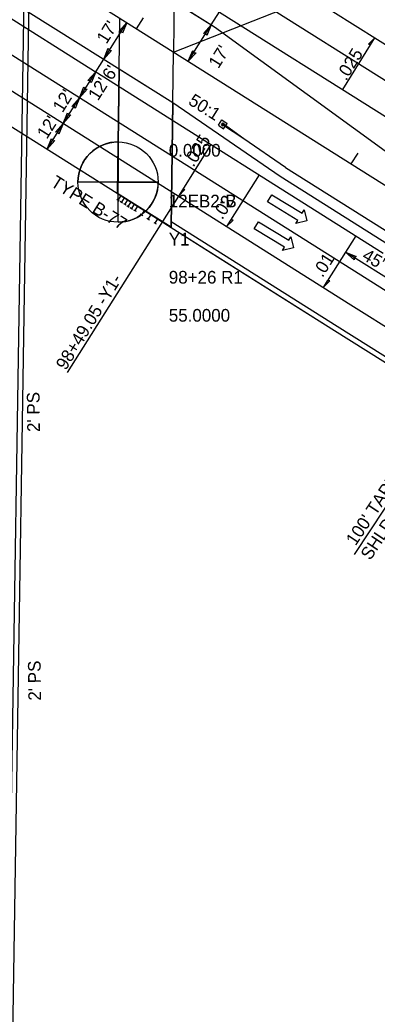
# Model space of a CAD drawing. Extents: x 2389694 to 2405615, y 546931 to 573532.
# Drawn here: x 2397764.3 to 2397905.2, y 552684.1 to 553075.7 of the extents above; entities that cross this region are included whole.
import ezdxf

# ---------------------------------------------------------------- set-up
doc = ezdxf.new("R2010")
doc.units = 0
for name, color, linetype in [('Boring Cell', 7, 'Continuous'), ('Old_Level_22', 7, 'Continuous'), ('Prop Approach Slab', 7, 'Continuous'), ('Prop Approach Slab Hatching', 7, 'Continuous'), ('Prop Cable Guiderail Anchor Unit CELL', 7, 'Continuous'), ('Prop Cable Guiderail Double Face', 7, 'Continuous'), ('Prop Conc Expressway Gutter', 7, 'Continuous'), ('Prop Dimension', 7, 'Continuous'), ('Prop Dimension Text', 7, 'Continuous'), ('Prop EOT', 7, 'Continuous'), ('Prop Guardrail', 7, 'Continuous'), ('Prop Horizontal Alignment', 7, 'Continuous'), ('Prop Horizontal Alignment Tick Small', 7, 'Continuous'), ('Prop Lane Arrow Through CELL', 7, 'Continuous'), ('Prop Lane Lines', 7, 'Continuous'), ('Prop Road Plan_ Boring - Labels from Geopak', 7, 'Continuous'), ('Prop SAU III Approach CELL', 7, 'Continuous'), ('Prop Super Arrow 1 Lane CELL', 7, 'Continuous'), ('Prop Superelevation Label', 7, 'Continuous')]:
    doc.layers.add(name, color=color, linetype=linetype)

msp = doc.modelspace()

# ---------------------------------------------------------------- linework, layer by layer
at = {"layer": 'Boring Cell'}
for p, q in [((2397803.04, 552996.02), (2397803.04, 553027.64)), ((2397803.22, 553027.64), (2397803.04, 553027.64)), ((2397818.85, 553011.83), (2397787.23, 553011.83)), ((2397818.85, 553011.83), (2397818.85, 553012.01))]:
    msp.add_line(p, q, dxfattribs=at)
for points in [[(2397803.04, 553027.64), (2397803.04, 553011.83), (2397787.23, 553011.83)], [(2397803.04, 552996.02), (2397803.04, 553011.83), (2397818.85, 553011.83)]]:
    msp.add_lwpolyline(points, dxfattribs=at)
msp.add_circle((2397803.04, 553011.83), 15.81, dxfattribs=at)
for start, end in [(89.3557, 180), (270, 0.6443)]:
    msp.add_arc((2397803.04, 553011.83), 15.81, start, end, dxfattribs=at)
at = {"layer": 'Prop Approach Slab'}
for p, q in [((2397670.86, 553139.97), (2397824.62, 553043.14)), ((2397670.16, 553090.81), (2397823.92, 552993.99)), ((2397803.47, 553056.47), (2397802.76, 553007.31))]:
    msp.add_line(p, q, dxfattribs=at)
at = {"layer": 'Prop Approach Slab Hatching'}
msp.add_lwpolyline([(2397803.47, 553056.47), (2397824.62, 553043.14), (2397823.92, 552993.99), (2397802.76, 553007.31)], close=True, dxfattribs=at)
at = {"layer": 'Prop Cable Guiderail Anchor Unit CELL'}
for p, q in [((2397842.59, 553034.24), (2397844.01, 553036.3)), ((2397843.77, 553034.31), (2397844.36, 553035.17)), ((2397844.01, 553036.3), (2397846.06, 553034.88)), ((2397844.29, 553033.96), (2397844.88, 553034.81)), ((2397844.36, 553035.17), (2397844.88, 553034.81)), ((2397852.56, 553028.89), (2397844.49, 553034.76)), ((2397844.65, 553032.82), (2397846.06, 553034.88)), ((2397842.59, 553034.24), (2397844.65, 553032.82)), ((2397843.77, 553034.31), (2397844.29, 553033.96)), ((2397852.56, 553028.89), (2397844.19, 553034.37)), ((2397852.56, 553028.89), (2397844.33, 553034.56)), ((2397869.03, 553017.54), (2397852.56, 553028.89)), ((2397852.56, 553028.89), (2397852.56, 553028.89))]:
    msp.add_line(p, q, dxfattribs=at)
at = {"layer": 'Prop Cable Guiderail Double Face'}
msp.add_line((2397869.03, 553017.54), (2397911.83, 552990.59), dxfattribs=at)
at = {"layer": 'Prop Conc Expressway Gutter'}
for p, q in [((2397824.01, 552996.26), (2397889.45, 552955.05)), ((2397889.45, 552955.05), (2397919.6, 552936.07))]:
    msp.add_line(p, q, dxfattribs=at)
at = {"layer": 'Prop Dimension'}
for p, q in [((2397825.91, 553132.18), (2397824.91, 553063.05)), ((2397824.91, 553063.05), (2397970.44, 553120.26)), ((2397839.78, 553073.78), (2397842.98, 553078.86)), ((2397797.41, 553060.28), (2397806.47, 553074.66)), ((2397802.76, 553007.31), (2397803.75, 553076.38)), ((2397830.72, 553059.39), (2397839.78, 553073.78)), ((2397823.92, 552993.99), (2397824.91, 553063.05)), ((2397794.22, 553055.2), (2397797.41, 553060.28)), ((2397787.82, 553045.05), (2397794.22, 553055.2)), ((2397781.43, 553034.89), (2397787.82, 553045.05)), ((2397775.05, 553024.76), (2397781.43, 553034.89)), ((2397826.81, 553006.32), (2397783.04, 552936.81)), ((2397930.74, 552960.25), (2397892.66, 552984.22)), ((2397924.03, 552907.26), (2397896.07, 552865.17))]:
    msp.add_line(p, q, dxfattribs=at)
for points in [[(2397803.42, 553071.27), (2397806.47, 553074.66), (2397804.74, 553070.41), (2397804.37, 553071.32)], [(2397836.73, 553070.38), (2397839.78, 553073.78), (2397838.05, 553069.52), (2397837.68, 553070.44)], [(2397800.47, 553063.67), (2397797.41, 553060.28), (2397799.15, 553064.53), (2397799.52, 553063.62)], [(2397833.78, 553062.79), (2397830.72, 553059.39), (2397832.46, 553063.65), (2397832.83, 553062.74)], [(2397791.16, 553051.81), (2397794.22, 553055.2), (2397792.48, 553050.95), (2397792.11, 553051.86)], [(2397790.88, 553048.44), (2397787.82, 553045.05), (2397789.56, 553049.3), (2397789.93, 553048.39)], [(2397784.77, 553041.65), (2397787.82, 553045.05), (2397786.09, 553040.79), (2397785.72, 553041.7)], [(2397784.48, 553038.29), (2397781.43, 553034.89), (2397783.16, 553039.15), (2397783.53, 553038.23)], [(2397778.37, 553031.5), (2397781.43, 553034.89), (2397779.69, 553030.64), (2397779.32, 553031.55)], [(2397778.1, 553028.16), (2397775.05, 553024.76), (2397776.78, 553029.02), (2397777.15, 553028.1)], [(2397896.06, 552981.17), (2397892.66, 552984.22), (2397896.92, 552982.49), (2397896, 552982.12)]]:
    msp.add_lwpolyline(points, close=True, dxfattribs=at)
at = {"layer": 'Prop EOT'}
for p, q in [((2397759.5, 552671.75), (2397782.16, 554116.88)), ((2397761.5, 552671.72), (2397784.16, 554116.85)), ((2396983.48, 553620.08), (2397932.08, 553022.75)), ((2396958.97, 553581.15), (2397793.8, 553055.47)), ((2397200.04, 553400.99), (2397894.78, 552963.52)), ((2397640.1, 553234.97), (2397944.87, 553043.06)), ((2397825.2, 553082.96), (2397841.06, 553072.97)), ((2397841.06, 553072.97), (2397967.73, 552980.9)), ((2397793.84, 553055.44), (2397907.57, 552983.82)), ((2397824.63, 553043.21), (2397866.9, 553014.16)), ((2397866.9, 553014.16), (2397909.7, 552987.21)), ((2397823.92, 552993.96), (2397888.38, 552953.36)), ((2397894.78, 552963.51), (2397922, 552946.37)), ((2397888.39, 552953.36), (2397915.61, 552936.22))]:
    msp.add_line(p, q, dxfattribs=at)
at = {"layer": 'Prop Guardrail'}
for p, q in [((2397819.91, 553086.29), (2397841.06, 553072.97)), ((2397841.06, 553072.97), (2397967.73, 552980.9)), ((2397818.63, 552997.32), (2397839.76, 552983.98)), ((2397839.76, 552983.98), (2397888.39, 552953.36)), ((2397888.39, 552953.36), (2397915.61, 552936.22))]:
    msp.add_line(p, q, dxfattribs=at)
at = {"layer": 'Prop Horizontal Alignment'}
msp.add_line((2396971.22, 553600.62), (2397933.44, 552994.72), dxfattribs=at)
at = {"layer": 'Prop Horizontal Alignment Tick Small'}
for p, q in [((2397810.35, 553072.23), (2397813.01, 553076.46)), ((2397894.97, 553018.94), (2397897.63, 553023.17))]:
    msp.add_line(p, q, dxfattribs=at)
at = {"layer": 'Prop Lane Arrow Through CELL'}
for p, q in [((2397861.91, 553003.99), (2397863.61, 553006.81)), ((2397873.89, 552996.74), (2397861.91, 553003.99)), ((2397863.61, 553006.81), (2397875.59, 552999.56)), ((2397875.59, 552999.56), (2397876.37, 553000.85)), ((2397876.37, 553000.85), (2397877.46, 552996.56)), ((2397856.66, 552993.39), (2397858.37, 552996.21)), ((2397858.37, 552996.21), (2397870.35, 552988.97)), ((2397873.11, 552995.46), (2397873.89, 552996.74)), ((2397877.46, 552996.56), (2397873.11, 552995.46)), ((2397868.64, 552986.15), (2397856.66, 552993.39)), ((2397870.35, 552988.97), (2397871.12, 552990.25)), ((2397871.12, 552990.25), (2397872.21, 552985.97)), ((2397867.86, 552984.86), (2397868.64, 552986.15)), ((2397872.21, 552985.97), (2397867.86, 552984.86))]:
    msp.add_line(p, q, dxfattribs=at)
at = {"layer": 'Prop Lane Lines'}
for p, q in [((2396989.87, 553630.23), (2397938.47, 553032.9)), ((2396952.57, 553571), (2397901.17, 552973.67)), ((2397901.18, 552973.67), (2397928.4, 552956.53))]:
    msp.add_line(p, q, dxfattribs=at)
at = {"layer": 'Prop SAU III Approach CELL'}
for p, q in [((2397802.76, 553007.31), (2397818.63, 552997.32)), ((2397802.54, 553005.09), (2397803.51, 553004.48)), ((2397804.09, 553006.48), (2397803.02, 553004.78)), ((2397803.86, 553004.26), (2397804.83, 553003.65)), ((2397805.41, 553005.64), (2397804.34, 553003.95)), ((2397805.18, 553003.42), (2397806.15, 553002.81)), ((2397806.73, 553004.81), (2397805.67, 553003.12)), ((2397808.05, 553003.98), (2397806.99, 553002.29)), ((2397806.5, 553002.59), (2397807.47, 553001.98)), ((2397807.83, 553001.76), (2397808.79, 553001.15)), ((2397809.38, 553003.15), (2397808.31, 553001.45)), ((2397809.15, 553000.93), (2397810.12, 553000.32)), ((2397810.7, 553002.31), (2397809.63, 553000.62)), ((2397813.34, 553000.65), (2397812.28, 552998.96)), ((2397811.79, 552999.26), (2397812.76, 552998.65)), ((2397814.44, 552997.6), (2397815.41, 552996.99)), ((2397815.99, 552998.98), (2397814.92, 552997.29)), ((2397817.08, 552995.93), (2397818.05, 552995.32)), ((2397818.63, 552997.32), (2397817.57, 552995.63))]:
    msp.add_line(p, q, dxfattribs=at)
at = {"layer": 'Prop Super Arrow 1 Lane CELL'}
for p, q in [((2397891.61, 553048.23), (2397904.25, 553068.63)), ((2397839.59, 553026.63), (2397826.81, 553006.32)), ((2397858.63, 553014.64), (2397845.85, 552994.33)), ((2397896.71, 552990.66), (2397883.92, 552970.35))]:
    msp.add_line(p, q, dxfattribs=at)
for points in [[(2397904.25, 553068.63), (2397901.73, 553066.08), (2397902.7, 553066.13)], [(2397826.81, 553006.32), (2397829.35, 553008.85), (2397828.38, 553008.81)], [(2397845.85, 552994.33), (2397848.39, 552996.86), (2397847.42, 552996.83)], [(2397883.92, 552970.35), (2397886.47, 552972.89), (2397885.5, 552972.85)]]:
    msp.add_lwpolyline(points, close=True, dxfattribs=at)

# ---------------------------------------------------------------- texts
at = {"layer": 'Old_Level_22'}
for s, p in [("100' TAPER &", (2397896.67, 552868.26)), ('SHLDR TRANS', (2397902.46, 552862.52))]:
    msp.add_text(s, height=5, rotation=56.3289, dxfattribs=at).set_placement(p)
at = {"layer": 'Prop Dimension Text'}
for s, rotation, p in [("17'", 57.9134, (2397798.48, 553065.9)), ("17'", 57.9134, (2397842.59, 553056.23)), ("6'", 57.9134, (2397800.66, 553051.55)), ("12'", 57.9134, (2397795.13, 553043.53)), ("12'", 57.9134, (2397781.15, 553038.86)), ('50:1', 327.8032, (2397830.37, 553042.7)), ("12'", 57.9134, (2397774.97, 553028.43)), ('TYPE B-77', 327.8032, (2397776.11, 553010.5)), ("45' TYP.", 329.5519, (2397898.85, 552981.57)), ('98+49.05 -Y1-', 58.3838, (2397782.45, 552937.41)), ("2' PS", 90.5836, (2397772.24, 552913.39)), ("2' PS", 90.5836, (2397772.68, 552807.58))]:
    msp.add_text(s, height=5, rotation=rotation, dxfattribs=at).set_placement(p)
at = {"layer": 'Prop Road Plan_ Boring - Labels from Geopak'}
for s, p in [('0.0000', (2397823.04, 553021.83)), ('12EB2-B', (2397823.04, 553001.83)), ('Y1', (2397823.04, 552986.83)), ('98+26 R1', (2397823.04, 552971.83)), ('55.0000', (2397823.04, 552956.83))]:
    msp.add_text(s, height=5, dxfattribs=at).set_placement(p)
at = {"layer": 'Prop Superelevation Label'}
for s, rotation, p in [('.025', 58.2085, (2397892.95, 553051.41)), ('.025', 57.8016, (2397832.77, 553017.44)), ('.02', 57.8016, (2397844.12, 552996.72)), ('.01', 57.8016, (2397883.65, 552973.94))]:
    msp.add_text(s, height=5, rotation=rotation, dxfattribs=at).set_placement(p)

doc.saveas('drawing.dxf')
